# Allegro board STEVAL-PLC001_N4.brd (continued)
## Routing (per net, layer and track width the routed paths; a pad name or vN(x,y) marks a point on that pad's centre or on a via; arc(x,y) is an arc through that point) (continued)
FMC_CTRL.SDNRAS: length 21.1
  TOP w0.2: v2(39.71,69.4) 41.21,70.9 44.6,70.9 46.3,69.2 v1(46.91,69.2)
  BOTTOM w0.2: v2(39.71,69.4) 38.51,70.6 35.22,70.6 34.77,70.15 34.32,70.15 34.27,70.2 U19.19 ; U27.49 50.41,69.5 50.11,69.2 v1(46.91,69.2)
FMC_CTRL.SDNWE: length 21.2
  TOP w0.18: v2(35.31,68.8) 39.01,65.1 45.7,65.1 46.38,65.78 v1(46.91,65.78)
  BOTTOM w0.16: v1(46.91,65.78) 47.39,65.78 48.11,66.5 U27.43 ; v2(35.31,68.8) 34.91,69.2 U19.17
FMC_DATA.D0: length 46.5
  POWER PLANE w0.152: v1(35.12,61.79) 35.88,62.55 35.88,62.88 35.91,62.9 35.91,63.77 36.47,64.32 36.47,75.23 42.43,81.19 42.43,81.2 42.86,81.63 42.87,81.63 45.58,84.34 56.54,84.34 56.54,84.34 59.36,84.34 59.38,84.35 59.71,84.35 v1(60.41,85.05)
  BOTTOM w0.152: U19.2 35.03,61.7 v1(35.12,61.79) ; v1(60.41,85.05) 60.07,84.71 60.07,84.57 59.86,84.35 U27.85
FMC_DATA.D1: length 44.8
  POWER PLANE w0.152: v1(60.48,84.24) 60.03,84.24 59.84,84.05 59.5,84.05 59.49,84.04 56.67,84.04 56.66,84.03 45.74,84.03 44.85,83.14 44.84,83.14 43.64,81.94 43.61,81.94 42.99,81.33 42.98,81.33 42.73,81.08 42.73,81.07 36.77,75.1 36.77,64.2 36.76,64.19 36.76,63.9 36.31,63.45 v1(36.31,62.7)
  BOTTOM w0.152: v1(36.31,62.7) U19.4 ; U27.86 60.36,84.12 v1(60.48,84.24)
FMC_DATA.D2: length 59.6
  POWER PLANE w0.16: v1(71.31,78.8) 69.92,78.8 67.25,81.47 67.25,81.87 65.66,83.46 64.41,83.46 63.43,84.44 63.41,84.44 62.06,85.79 61.88,85.79 61.82,85.86 59.92,85.86 59.01,84.95 56.29,84.95 56.29,84.94 45.29,84.94 35.81,75.47 35.81,69.06 35.85,69.02 35.85,68.58 35.81,68.54 35.81,65.1 35.11,64.4 v1(35.11,63.3)
  BOTTOM w0.152: U27.114 72.09,78.5 71.79,78.8 v1(71.31,78.8)
  BOTTOM w0.16: U19.5 35.01,63.2 v1(35.11,63.3)
FMC_DATA.D3: length 58.6
  POWER PLANE w0.152: 36.16,68.42 36.16,75.38 45.42,84.64 56.41,84.64 56.42,84.64 59.24,84.64 60.08,85.48
  POWER PLANE w0.16: v1(35.71,64.2) 36.16,64.65 36.16,68.42 ; v1(71.66,78) 70.28,78 66.94,81.34 66.94,81.74 65.53,83.15 64.28,83.15 63.3,84.13 63.28,84.13 61.93,85.48 60.08,85.48
  BOTTOM w0.152: U27.115 v1(71.66,78)
  BOTTOM w0.16: v1(35.71,64.2) U19.7
FMC_DATA.D4: length 23.2
  TOP w0.152: v2(47.01,72.86) 42.42,72.86 39.49,69.93 39.49,69.93 38.52,68.96 38.52,68.57 v2(37.93,67.98)
  BOTTOM w0.152: v2(47.01,72.86) 48.04,72.86 49.38,74.2 50.87,74.2 51.07,74 U27.58 ; v2(37.93,67.98) 37.52,67.57 37.52,67.5 34.72,64.7 U19.8
FMC_DATA.D5: length 22.9
  TOP w0.152: v2(47.82,73.39) 47.4,73.8 42.72,73.8 v1(37.91,69) 37.91,68.98
  BOTTOM w0.152: v2(47.82,73.39) 47.83,73.4 47.94,73.4 49.04,74.5 49.25,74.5 49.25,74.5 51.07,74.5 51.07,74.5 U27.59 ; U19.10 34.61,65.7 37.66,68.75
  BOTTOM w0.16: v1(37.91,69) 37.66,68.75
FMC_DATA.D6: length 22.8
  TOP w0.152: 37.81,69.7 42.3,74.2 v2(47.81,74.2)
  TOP w0.16: v1(37.52,69.42) 37.81,69.7
  BOTTOM w0.152: v2(47.81,74.2) 48.31,74.2 49.11,75 U27.60 ; U19.11 34.3,66.2 v1(37.52,69.42) 37.66,69.56
FMC_DATA.D7: length 27.1
  TOP w0.16: 45.65,78.09 v2(47.82,78.09)
  TOP w0.17: 45.65,78.09 39.7,78.09 33.91,72.3 33.91,71.48 33.89,71.45 33.89,71.14 33.91,71.12 v2(33.91,67.2)
  BOTTOM w0.16: v2(47.82,78.09) 48.22,78.09 49.81,76.5 U27.63
  BOTTOM w0.17: v2(33.91,67.2) U19.13
FMC_DATA.D8: length 17.3
  POWER PLANE w0.18: v1(52.98,77) 52.49,77 52.49,77 49.52,77 48.03,75.5 48.03,75.48 46.46,73.91 46.46,71.75 46.91,71.3 v1(46.91,70.8)
  BOTTOM w0.18: U19.74 45.04,67.2 45.71,67.87 45.71,69.11 46.91,70.31 v1(46.91,70.8)
  BOTTOM w0.2: v1(52.98,77) U27.64
FMC_DATA.D9: length 16.7
  POWER PLANE w0.18: v1(50.91,77.5) 49.56,77.5 47.7,75.63 47.7,75.61 45.46,73.38 45.46,70.16 45.51,70.11 v1(45.51,66.25)
  BOTTOM w0.2: v1(50.91,77.5) U27.65 ; v1(45.51,66.25) 45.46,66.25 45.41,66.2 U19.76
FMC_DATA.D10: length 19.9
  POWER PLANE w0.18: v1(52.98,78) 49.59,78 47.37,75.77 47.37,75.75 45.06,73.45 45.06,65.8 v1(45.26,65.6)
  BOTTOM w0.2: U19.77 45.06,65.7 45.16,65.6 v1(45.26,65.6) ; v1(52.98,78) U27.66
FMC_DATA.D11: length 20.2
  POWER PLANE w0.18: v1(45.51,64.65) 45.02,64.65 44.7,64.97 44.7,73.55 47.04,75.89 47.04,75.91 49.63,78.5 v1(50.91,78.5)
  BOTTOM w0.2: v1(45.51,64.65) 45.46,64.7 U19.79 ; U27.67 v1(50.91,78.5)
FMC_DATA.D12: length 22.9
  POWER PLANE w0.18: v1(52.98,79) 49.66,79 46.71,76.05 46.71,76.02 44.3,73.62 44.3,70.8 44.26,70.76 44.26,64.89 44.98,64.17 v1(45.16,64.17)
  BOTTOM w0.2: U27.68 v1(52.98,79) ; U19.80 45.13,64.2 v1(45.16,64.17)
FMC_DATA.D13: length 29.9
  BOTTOM w0.16: U27.77 55.86,66.23 52.43,62.8 45.37,62.8 44.97,63.2 U19.82
FMC_DATA.D14: length 30.7
  BOTTOM w0.16: U27.78 56.36,66.3 52.26,62.2 45.53,62.2 45.03,62.7 U19.83
FMC_DATA.D15: length 31.1
  BOTTOM w0.17: U19.85 52.21,61.7 56.86,66.34 56.86,66.73 56.86,66.74 U27.79
I0.0: length 32.7
  TOP w0.2: R7.1 31.91,104.55 v2(33.41,106.05)
  BOTTOM w0.25: v2(33.41,106.05) 34.11,106.75 34.11,114.2 32.16,116.15 19.34,116.15
  BOTTOM w0.5: J1.8 19.34,116.15
I0.1: length 22
  TOP w0.2: v2(29.71,105.15) 29.71,103.55 30.31,102.95 R9.1
  BOTTOM w0.25: 23.87,115.6 28.06,115.6 29.71,113.95 v2(29.71,105.15)
  BOTTOM w0.5: J1.7 23.87,115.6
I0.2: length 11.9
  TOP w0.2: R11.1 v2(28.71,105)
  BOTTOM w0.25: 28.71,110.94 v2(28.71,105)
  BOTTOM w0.5: J1.6 28.71,110.94
I0.3: length 13.5
  TOP w0.2: 27.11,104.29 R12.1
  TOP w0.25: v2(30.31,106.24) 29.06,106.24 27.11,104.29
  BOTTOM w0.25: 31.59,113.14 J1.5 ; v2(30.31,106.24) 31.59,107.52 31.59,108.98
  BOTTOM w0.5: 31.59,108.98 31.59,113.14
I0.4: length 21.7
  TOP w0.25: R14.1 25.46,102.88 24.96,103.38 24.96,108.07 25.21,108.32 v2(34.97,108.32)
  BOTTOM w0.25: v2(34.97,108.32) 34.97,109.26 36.67,110.96 ; 36.67,113.14 J1.4
  BOTTOM w0.5: 36.67,110.96 36.67,113.14
I0.5: length 25.8
  TOP w0.25: R17.1 23.86,108 24.77,108.91 v2(36.63,108.91)
  BOTTOM w0.25: v2(36.63,108.91) 37.57,108.91 39.16,110.5 39.16,110.57
  BOTTOM w0.5: 39.16,110.57 J1.3
I0.6: length 32.1
  TOP w0.25: v2(41.31,109.66) 24.49,109.66 23.46,108.62 23.46,104.2 22.31,103.05 R19.1
  BOTTOM w0.25: v2(41.31,109.66) 43.28,109.66 44.81,111.18 44.85,111.18
  BOTTOM w0.5: 44.85,111.18 J1.2
I0.7: length 38.3
  TOP w0.25: J1.1 49.21,110.46 24.51,110.46 23.01,108.96 23.01,105.1 20.76,102.85 R22.1
I1.0H: length 16.7
  TOP w0.25: 54.85,101.5 54.89,101.54 C20.1 56.74,101.82 56.75,101.82 57.09,102.16 57.09,102.17 57.81,102.89 57.81,108.53 J6.2
  TOP w0.3: U4.6 U4.7
I1.0L: length 12.7
  TOP w0.25: C20.2 55.98,102.46 55.55,102.02 U4.8
  TOP w0.3: v2(56.91,103.2) 56.46,102.75 C20.2
  BOTTOM w0.25: v2(56.91,103.2) 58.91,105.2 63.46,105.2 J6.5
I1.1H: length 25.8
  TOP w0.25: C23.1 64.15,99.04 67.86,102.75 J6.1
  TOP w0.3: C23.1 55.46,99.04 55.45,99.02 U4.2 U4.3
I1.1L: length 17.8
  TOP w0.25: U4.4 55.91,100.02 55.97,99.96 C23.2
  TOP w0.3: C23.2 56.56,100.05 57.06,100.55 v2(57.06,100.71)
  BOTTOM w0.25: v2(57.06,100.71) 57.82,99.95 67.01,99.95 J6.4
I1.2H: length 31.7
  TOP w0.2: C26.1 94.92,101.44 94.81,101.55 U5.7 U5.6
  TOP w0.25: C26.1 96.12,101.44 96.31,101.62 96.31,102.9 92.91,106.3 80.85,106.3 J7.3
I1.2L: length 23.4
  TOP w0.2: U5.8 94.61,102.05 94.92,102.36 C26.2
  TOP w0.25: J7.6 77.75,105.5 92.37,105.5 C26.2
I1.3H: length 30
  TOP w0.25: J7.2 85.18,107.05 93.36,107.05 96.91,103.5 96.91,100.15 95.8,99.04 C28.1
  TOP w0.3: C28.1 95.5,99.05 U5.2 U5.3
I1.3L: length 19.9
  TOP w0.3: v2(95.81,100.7) 95.81,100.4 95.51,100.1 C28.2 95.4,99.96 95.31,100.05 U5.4
  BOTTOM w0.25: J7.5 82.53,105.2 91.31,105.2 92.51,104 92.68,104 94.66,102.01 94.66,101.84 v2(95.81,100.7)
I2C1_SCL: length 17.2
  POWER PLANE w0.16: v1(75.41,82.45) 75.36,82.45 74.17,81.26 74.17,68.16 74.27,68.07 v1(74.27,67.59)
  BOTTOM w0.16: v1(75.41,82.45) R105.2 ; U27.136 74.01,67.5 74.1,67.59 v1(74.27,67.59)
I2C1_SDA: length 15.5
  POWER PLANE w0.16: v1(75.41,79.9) 74.48,78.97 74.48,75.63 74.7,75.41 74.7,67.28 v1(74.27,66.85)
  BOTTOM w0.16: v1(74.27,66.85) 74.12,67 U27.137 ; v1(75.41,79.9) R108.2
IN1_FLT: length 22.4
  TOP w0.16: R33.1 75.37,22.65 75.29,22.57 74.26,22.57 73.76,23.07 C33.2 73.24,22.57 72.82,22.57 72.64,22.39 72.48,22.39 72.14,22.05 U8.4
  TOP w0.2: 78,25.15 77.6,24.75 77.51,24.75 76.49,23.73 76.45,23.73 R33.1 ; 78.21,25.15 D17.A
  TOP w0.3: D17.A 77.18,25.15 v1(76.49,24.46)
  LOGIC_PLANE w0.2: v1(67.71,20.64) 67.71,21.82 69.1,23.2 71.11,23.2 71.31,23.4 75.93,23.4 76.49,23.96 v1(76.49,24.46)
  BOTTOM w0.2: v1(67.71,20.64) 67.71,20.75 68,21.04 R57.2
IN2_FLT: length 20.4
  TOP w0.16: 72.21,25.14 72.21,25.15 72.59,25.53 72.59,25.83 72.86,26.1 73.31,26.1 73.56,25.85 73.56,25.03 74.28,24.31 74.28,24.29 R35.1 ; 72.82,23.09 C32.2 ; 72.82,23.09 72.82,23.01 72.61,22.8 72.46,22.8 72.04,22.39 71.9,22.39 71.79,22.27 71.49,21.97 U8.5 ; 72.82,23.09 72.39,23.52 72.39,24.31 72.21,24.49 72.21,24.75
  TOP w0.2: v1(72.11,25.77) 72.11,25.25 72.21,25.15
  TOP w0.25: 72.21,24.75 72.21,25.14 D18.A
  BOTTOM w0.2: R56.2 66.57,21.53 66.57,22.22 66.75,22.4 66.75,22.96 66.51,23.2 66.51,25.57 66.71,25.77 v1(72.11,25.77)
IN3_FLT: length 29.2
  TOP w0.2: C38.2 70.91,22.75 70.83,22.67 U8.6 ; C38.2 v1(71.25,22.75) ; C38.2 R41.1 ; 71.91,22.87 71.91,23.04 R41.1 ; R41.1 71.86,22.98 71.79,22.91 ; D19.A 70.7,25.62 70.71,25.63 70.71,25.64 ; 70.71,25.64 v3(70.71,26.25) 70.7,26.24 70.7,25.63 70.71,25.64
  POWER PLANE w0.2: v3(70.71,26.25) 70.71,25.45 71.79,24.37 71.79,22.91 71.42,22.91 v1(71.25,22.75)
  POWER PLANE w0.3: v3(70.71,26.25) 70.71,26.91 69,28.62 60.29,28.62 TP8.1
  LOGIC_PLANE w0.2: v1(71.25,22.75) 71.61,22.39 72.06,22.39 73.35,21.1 73.35,20.94 v1(73.85,20.44)
  BOTTOM w0.2: R53.2 73.46,20.83 v1(73.85,20.44)
IN4_FLT: length 18.2
  TOP w0.16: U8.7 69.96,21.26 69.96,20.76 69.77,20.57 69,20.57 68.65,20.22 68.65,19.74 v1(68.31,19.4)
  TOP w0.2: v1(69.06,22.52) R43.1 C39.2 69.96,22.84 70.16,22.64 70.16,22.6 70.18,22.58 U8.7
  TOP w0.25: D20.A 64.41,25.11 v1(64.41,25.6)
  POWER PLANE w0.2: 64.68,25.6 66.52,25.6 69.06,23.05 v1(69.06,22.52)
  POWER PLANE w0.25: 64.68,25.6 v1(64.41,25.6)
  BOTTOM w0.2: R50.2 72.22,20.45 69.36,20.45 v1(68.31,19.4)
IO-RST: length 48.4
  LOGIC_PLANE w0.16: v1(65.33,87.86) 65.33,88.34 67.57,90.57 83.27,90.57 89.91,83.93 89.91,76.21 89.94,76.18 89.94,70.52 90.64,69.82 v2(90.64,69)
  BOTTOM w0.152: 90.67,69.12 90.64,69.09 v2(90.64,69)
  BOTTOM w0.16: v1(65.33,87.86) 65.33,87.61 66.01,86.93 R164.2
  BOTTOM w0.3: R122.1 R123.1
IRQ: length 116.4
  POWER PLANE w0.16: v1(81.91,55.52) 81.32,56.1 v1(81.32,86.6)
  LOGIC_PLANE w0.2: v1(71.71,51.3) 72.41,51.3 76.61,55.5 81.39,55.5 81.41,55.52 v1(81.91,55.52) ; v1(39.61,50.3) 39.11,49.8 39.11,48.25 41.43,45.93 46.43,45.93 v1(46.78,45.58)
  BOTTOM w0.16: 89.97,56.4 88.91,56.4 88.03,55.52 v1(81.91,55.52) ; v1(81.32,86.6) 80.93,86.2 76.53,86.2 75.81,86.92 74.52,86.92 R162.2
  BOTTOM w0.18: 89.97,56.4 R134.1
  BOTTOM w0.2: R99.2 38.31,48.54 38.31,49 v1(39.61,50.3) 38.21,50.3 36.71,51.8 34.17,51.8 ; v1(46.78,45.58) 50.33,45.58 52.31,43.6 61.37,43.6 62.77,45 69.83,45 70.17,45.34 71.45,45.34 72.51,46.4 72.51,49.8 71.71,50.6 v1(71.71,51.3)
  BOTTOM w0.3: R187.1 34.17,51.8
L+ON: length 90.7
  TOP w0.2: v2(58.71,73.6) 58.28,73.17 58.28,73.16 R165.2 54.62,70.09 54.51,70.2 v2(54.51,79.6)
  LOGIC_PLANE w0.2: v1(71.51,66.5) 72.01,66.5 72.11,66.4 75.58,66.4 75.62,66.36 76.35,66.36 77.31,65.4 v1(78.11,65.4) ; v1(49.91,90.8) 51.31,89.4 51.31,88 54.51,84.8 v2(54.51,79.6)
  LOGIC_PLANE w0.3: v1(37.51,89.6) 36.21,88.3 36.16,88.3 v1(35.81,87.95)
  BOTTOM w0.2: v2(58.71,73.6) 65.81,66.5 v1(71.51,66.5) ; v1(37.51,89.6) 38.71,90.8 v1(49.91,90.8)
  BOTTOM w0.25: v1(78.11,65.4) 78.48,65.77 82.67,65.77 83.11,65.33 83.11,63 84.98,61.12 88.01,61.12 88.01,61.12 89.45,61.12 R131.1 91.51,59.06 91.51,55.44 R135.1
  BOTTOM w0.3: R140.1 35.37,87.95 v1(35.81,87.95)
LCD_BLUE2: length 18
  TOP w0.16: U17.13 46.85,58.08 46.94,57.99 46.94,57.99 49.6,55.34 49.68,55.25 50.21,55.25 50.46,55.25 50.47,55.25 50.5,55.25 50.77,55.25 50.79,55.25 51.06,55.25 51.89,55.25 53.3,53.84 54.01,53.84 54.27,53.58 54.27,53.57 54.39,53.45 U15.23
  TOP w0.18: v1(50.25,48.66) 51.18,48.66 53.27,50.75 53.27,50.78 53.53,51.04 53.56,51.04 54.39,51.87 U15.23
  BOTTOM w0.18: R193.1 v1(50.25,48.66)
LCD_BLUE3: length 11.7
  TOP w0.152: U17.14 46.88,58.48 49.8,55.56 50.33,55.56 50.63,55.56 50.63,55.56 51.03,55.56 52.28,55.56 53.66,54.18 54.48,54.18 54.89,53.77 U15.24
LCD_BLUE4: length 12.3
  TOP w0.152: U17.15 47,58.88 50.02,55.86 50.33,55.86 50.56,55.86 50.75,55.86 50.96,55.86 51.16,55.86 52.4,55.86 53.78,54.48 54.68,54.48 55.39,53.77 U15.25
LCD_BLUE5: length 13
  TOP w0.152: U15.26 55.89,53.77 54.88,54.78 53.91,54.78 52.53,56.16 51.09,56.16 50.88,56.16 50.69,56.16 50.46,56.16 50.14,56.16 47.03,59.28 U17.16
LCD_BLUE6: length 6.8
  TOP w0.152: U16.9 52.78,56.49 53.04,56.23 55.37,56.23 56.14,55.46 56.14,55.14 56.39,54.89 U15.27
LCD_BLUE7: length 7.5
  TOP w0.152: U15.28 56.89,54.82 56.44,55.27 56.44,55.62 55.42,56.64 53.92,56.64 53.85,56.7 53,56.7 52.81,56.89 U16.10
LCD_BLUE.B3: length 36.9
  TOP w0.152: v1(45.51,60.18) 45.7,60.37 46.78,60.37 46.97,60.18
  TOP w0.16: v3(44,58.56) 44.01,58.55 44.35,58.55 44.75,58.55 U17.3 ; 46.97,60.18 47.24,59.91 49.89,59.91 51.84,61.87 54.42,61.87 58.82,66.26 64.01,71.45 69.46,71.45 v1(70.51,72.5)
  POWER PLANE w0.16: v1(45.51,60.18) 44.46,60.18 44,59.72 v3(44,58.56)
  BOTTOM w0.16: v1(70.51,72.5) U27.126
LCD_BLUE.B4: length 36
  TOP w0.16: v1(69.11,72) 64.12,72 58.69,66.57 58.69,66.57 54.3,62.18 51.72,62.18 49.97,60.43 49.88,60.43 49.87,60.43 48.32,60.43 47.77,60.99 45.13,60.99 44.24,60.1 44.24,59.24 44.53,58.95 44.57,58.95 44.64,58.88 U17.2
  BOTTOM w0.16: U27.127 v1(69.11,72)
LCD_BLUE.B5: length 13.4
  TOP w0.152: U17.1 44.82,60.09 45.4,60.67 47.28,60.67 v1(47.55,60.4)
  LOGIC_PLANE w0.16: 49.81,63.5 47.55,61.24 v1(47.55,60.4)
  LOGIC_PLANE w0.17: v1(53.12,64.19) 52.71,64.6 50.91,64.6 49.81,63.5
  BOTTOM w0.17: U27.37 52.68,63.5 53.12,63.94 v1(53.12,64.19)
LCD_BLUE.B6: length 35.3
  TOP w0.152: U16.8 51.07,56.49 50.98,56.49 50.91,56.56 50.88,56.56 50.33,56.56 48.47,58.42 v1(48.47,58.9)
  TOP w0.158: v1(49.76,60.86) 51.41,62.52 52.52,62.52
  TOP w0.16: v1(59.41,68.5) 59,68.09 58.2,68.09 52.63,62.52 52.52,62.52
  BOTTOM w0.158: v1(48.47,58.9) 48.47,59.58 v1(49.76,60.86)
  BOTTOM w0.16: v1(59.41,68.5) 59.41,69.1 59.71,69.4 62.39,69.4 65.79,66 U27.139
LCD_BLUE.B7: length 34.3
  TOP w0.16: v1(49.12,59.46) 49.12,58.22 49.64,57.71 50.42,56.93 50.98,56.93 51.02,56.89 U16.7 ; v1(49.15,60.86) 51.18,62.9 52.46,62.9 52.63,63.07 52.69,63.07 52.94,63.32 52.94,63.38 58.7,69.14 59.77,69.14 v1(60.11,68.8)
  POWER PLANE w0.18: v1(49.15,60.86) 49.15,59.97 49.12,59.95 v1(49.12,59.46)
  BOTTOM w0.16: U27.140 65.86,65.5 62.56,68.8 v1(60.11,68.8)
LCD_CLK: length 40.1
  TOP w0.152: v1(49.67,58.59) 49.67,58.11 49.73,58.06 49.73,58.05 49.94,57.84 50.49,57.29 U16.6
  POWER PLANE w0.16: v1(63.36,79.4) 63.36,60.2 62.61,59.45 61.09,59.45 61.06,59.42 60.7,59.42 60.67,59.45 59.38,59.45 58.56,60.27 56.64,60.27 56.23,59.86 54.65,59.86 54.02,59.23 50.79,59.23 50.15,58.59 v1(49.67,58.59)
  BOTTOM w0.16: U27.92 v1(63.36,79.4)
LCD_CLK2: length 8.7
  TOP w0.18: U15.30 57.89,54.28 57.44,54.73 57.44,55.73 57.31,55.86 57.31,55.87 57.05,56.13 57.04,56.13 56.22,56.95 54.05,56.95 53.98,57.02 53.13,57.02 52.86,57.29 U16.11
LCD_DE: length 12.9
  TOP w0.152: v1(60.83,60.56) 60.34,61.05 54.06,61.05 53.27,60.25 51.52,60.25 50.72,59.45 50.72,59.25 50.72,59.13 50.93,58.92 51.04,58.92 51.07,58.89 U16.2
  BOTTOM w0.2: v1(60.83,60.56) 60.86,60.59 U27.22
LCD_DE2: length 11.9
  TOP w0.18: U16.15 56.15,58.89 57.35,57.69 58.38,57.69 58.84,57.23 58.84,56.81 59.89,55.76 U15.34
LCD_DISP: length 36.1
  TOP w0.152: U16.5 50.52,57.69 50.49,57.71 50.11,58.09 50.11,59.71 50.17,59.76 50.63,60.22 51.51,61.1 51.97,61.56
  TOP w0.158: 55.59,62.59 54.55,61.56 51.97,61.56
  TOP w0.16: 55.59,62.59 58.94,65.95 58.95,65.95 64.14,71.14 70.05,71.14 v1(74.91,76)
  BOTTOM w0.16: v1(74.91,76) U27.119
LCD_DISP2: length 9.5
  TOP w0.152: U15.31 58.39,54.81 57.77,55.43 57.77,55.86 56.36,57.27 54.23,57.27 53.6,57.9 53.06,57.9 52.85,57.69 U16.12
LCD_GREEN2: length 12.6
  TOP w0.152: U15.15 50.39,53.46 50.13,53.72 49.32,53.72 49.07,53.72 49.05,53.74 48.76,54.03 48.75,54.03 48.75,54.03 48.66,54.12 47.49,55.29 41.36,55.29 41.06,55.59 U18.15
LCD_GREEN3: length 12.7
  TOP w0.152: U18.16 41.46,55.89 41.61,55.74 47.47,55.74 48.7,54.5 48.88,54.33 48.89,54.33 49.17,54.04 49.2,54.02 49.49,54.02 50.5,54.02 50.89,53.63 U15.16
LCD_GREEN4: length 8
  TOP w0.16: v1(46.4,56.21) 46.13,56.48 U17.9 ; U15.17 v1(51.39,52.01)
  LOGIC_PLANE w0.16: v1(46.4,56.21) 47.19,56.21 v1(51.39,52.01)
LCD_GREEN5: length 8
  TOP w0.152: U15.18 51.89,53.77 51.34,54.32 49.66,54.32 49.32,54.32 49.01,54.63 49,54.63 46.76,56.88 U17.10
LCD_GREEN6: length 8.7
  TOP w0.152: U15.19 52.39,53.77 51.53,54.62 49.83,54.62 49.45,54.62 49.14,54.93 49.13,54.93 46.78,57.28 U17.11
LCD_GREEN7: length 9.3
  TOP w0.152: U17.12 46.82,57.68 49.55,54.95 50.21,54.95 50.34,54.95 50.38,54.95 50.94,54.95 51.71,54.95 52.89,53.77 U15.20
LCD_GREEN.G2: length 14.3
  TOP w0.152: v1(42.11,60) 41.91,59.8 41.58,59.8 41.06,59.28 U18.2
  LOGIC_PLANE w0.152: v1(50.3,66.01) 49.97,65.67 49.93,65.67 45.26,61 43.36,61 42.7,60.34 42.45,60.34 v1(42.11,60)
  BOTTOM w0.152: v1(50.3,66.01) 50.81,66.01 50.81,66 U27.42
LCD_GREEN.G3: length 38.4
  TOP w0.152: 69.31,73 v1(68.92,73) 62.16,73 58.87,69.71 58.83,69.71 53.74,64.62 52.46,64.62 49.16,61.32 49.13,61.32 49.12,61.31 47.22,61.31 47.22,61.31 43.77,61.31 42.73,60.27 42.73,60.09 42.54,59.9 42.54,59.82 42.16,59.45 41.91,59.45 41.46,59 U18.1
  BOTTOM w0.16: v1(68.92,73) U27.125
LCD_GREEN.G4: length 35.7
  TOP w0.152: v1(42.08,58.85) 42.08,57.14 42.67,56.55 44.25,56.55 44.32,56.48 U17.8
  TOP w0.16: v1(42.31,60.8) 43.13,61.62 49,61.62 49.05,61.67 49.06,61.67 52.31,64.92 52.58,64.92 v1(53.29,65.62)
  POWER PLANE w0.152: v1(42.31,60.8) 41.94,60.43 41.93,60.43 41.68,60.18 41.68,59.71 42.08,59.32 v1(42.08,58.85)
  BOTTOM w0.152: v1(53.29,65.62) 53.89,66.22 53.89,78.82 53.21,79.5 U27.69
LCD_GREEN.G5: length 37.9
  TOP w0.152: U17.7 43.01,56.88 42.38,57.51 42.38,58.54 42.5,58.67 42.5,58.68 42.53,58.71 42.53,59.22 v1(42.87,59.55)
  TOP w0.16: v1(54.41,66.75) 53.73,66.07 53.01,66.07 48.89,61.95 46.99,61.95 46.99,61.95 v1(42.11,61.95) 42.06,61.95
  LOGIC_PLANE w0.152: v1(42.87,59.55) 42.83,59.55 42.81,59.57 41.93,59.57 41.68,59.82 41.68,59.83 41.54,59.97 41.54,61.38 41.77,61.61
  LOGIC_PLANE w0.16: v1(42.11,61.95) 41.77,61.61
  BOTTOM w0.152: v1(54.41,66.75) 54.41,78.73 53.14,80 U27.70
LCD_GREEN.G6: length 45.7
  TOP w0.152: v1(43.16,59.09) 43.16,59.09 43.16,58.91 42.8,58.56 42.8,58.54 42.68,58.42 42.68,58.1 43.5,57.28 U17.6
  TOP w0.16: v1(42.38,62.43) 42.86,62.43 42.88,62.45 48.95,62.45 52.96,66.46 52.96,66.97 53.21,67.22 53.78,67.22 62.96,76.4 65.81,76.4 v2(65.86,76.35)
  LOGIC_PLANE w0.152: v1(43.16,59.09) 42.5,59.09 42.32,59.27 41.81,59.27 41.79,59.29 41.42,59.29 41.23,59.48 41.23,61.92 41.74,62.43 v1(42.38,62.43)
  BOTTOM w0.152: v2(65.86,76.35) U27.97
LCD_GREEN.G7: length 46.6
  TOP w0.152: U17.5 43.79,57.68 v1(43.16,58.31)
  TOP w0.16: v1(41.96,63.08) 42.44,63.08 42.51,63.01 42.51,63.01 42.75,62.77 48.83,62.77 51.31,65.25 51.31,65.85 52.99,67.53 53.65,67.53 54.49,68.37 54.49,68.37 63.12,77 v1(71.96,77)
  LOGIC_PLANE w0.152: v1(43.16,58.31) 42.68,58.31 42.66,58.33 41.58,58.33 40.91,59 40.91,62.02 v1(41.96,63.08)
  BOTTOM w0.16: v1(71.96,77) U27.117
LCD_HSYNC: length 38.8
  TOP w0.152: 50.91,58.08 50.85,58.14 v1(50.67,58.14)
  TOP w0.16: 50.91,58.08 51.16,58.08 U16.4
  POWER PLANE w0.152: v1(65.36,82.4) 65.36,76.6 65.33,76.57 65.33,76.13 65.36,76.1 65.36,75.35 63.98,73.97 63.98,59.97 63.08,59.08 59.21,59.08 58.37,59.93 57.02,59.93 55.98,58.89 53.93,58.89 53.89,58.92 51.45,58.92 v1(50.67,58.14)
  BOTTOM w0.16: U27.96 v1(65.36,82.4)
LCD_HSYNC2: length 10.3
  TOP w0.152: U15.32 58.89,55.52 58.31,56.1 57.99,56.1 56.52,57.57 54.41,57.57 53.77,58.21 52.94,58.21 52.82,58.09 U16.13
LCD_INT: length 45.4
  TOP w0.16: U15.38 61.89,51.61 60.73,50.45 56.41,50.45 v1(55.53,49.57)
  POWER PLANE w0.16: v1(54.91,51.4) 54.91,51.88 55.68,52.65 57.58,52.65 64.63,59.7 64.63,71.92 66.21,73.5 v1(66.51,73.5)
  LOGIC_PLANE w0.16: v1(55.53,49.57) 54.91,50.2 v1(54.91,51.4)
  BOTTOM w0.2: v1(66.51,73.5) U27.124
LCD_RED2: length 19.3
  TOP w0.18: 38.66,55.28 U18.9
  TOP w0.2: 38.66,55.28 43.51,50.43 46.22,50.43 v1(47.22,51.43) 46.87,51.43 46.39,51.91 U15.7
  BOTTOM w0.2: v1(47.22,51.43) 46.6,50.81 46.07,50.81 44.51,49.25 R93.1
LCD_RED3: length 11.3
  TOP w0.16: U15.8 46.89,53.48 46.63,53.74 40.68,53.74 39.06,55.36 U18.10
LCD_RED4: length 11.4
  TOP w0.16: U18.11 39.46,55.4 40.81,54.05 46.68,54.05 46.82,54.05 47.39,53.48 U15.9
LCD_RED5: length 11.4
  TOP w0.16: U15.10 47.83,52.89 47.82,53.54 47.01,54.36 46.81,54.36 40.94,54.36 39.86,55.44 U18.12
LCD_RED6: length 11.5
  TOP w0.16: U15.11 48.39,53.47 47.19,54.67 46.94,54.67 41.06,54.67 40.26,55.48 U18.13
LCD_RED7: length 11.6
  TOP w0.16: U15.12 48.77,52.96 48.77,53.58 48.64,53.72 48.62,53.72 48.62,53.73 48.61,53.73 48.45,53.89 47.36,54.98 41.19,54.98 40.66,55.51 U18.14
LCD_RED.R2: length 21.5
  TOP w0.152: U18.8 38.66,58.83 38.38,59.11 37.55,59.11 37.03,58.59 v1(37.03,58.11)
  POWER PLANE w0.17: 53.95,58.08 53.93,58.07 53.92,58.07 v1(53.31,57.46) 52.83,57.46 52.73,57.36 39.53,57.36 38.31,58.59 37.51,58.59 v1(37.03,58.11)
  BOTTOM w0.2: v1(53.31,57.46) 53.42,57.46 53.62,57.66 53.62,57.67 53.64,57.69 53.64,57.77 R152.2
LCD_RED.R3: length 20.5
  TOP w0.152: v3(38.91,60.3) 38.91,59.42 39.06,59.27 U18.7
  TOP w0.16: v3(39.26,62.1) 40.76,63.6 42.56,63.6 43.06,63.1 43.28,63.1 43.29,63.09 48.71,63.09 50.91,65.29 v1(50.91,67.6)
  POWER PLANE w0.152: v3(38.91,60.3) 38.91,61.17 39.26,61.52 v3(39.26,62.1)
  BOTTOM w0.16: U27.46 51.31,68 v1(50.91,67.6)
LCD_RED.R4: length 19.1
  TOP w0.152: 49.75,64.56 49.75,64.89 v1(50.09,65.22)
  TOP w0.16: U18.6 39.46,60.8 38.76,61.5 38.76,61.84 38.72,61.88 38.72,62.32 40.35,63.95 42.76,63.95 43.3,63.41 43.41,63.41 43.42,63.4 48.59,63.4 49.75,64.56
  BOTTOM w0.16: v1(50.09,65.22) 50.57,65.22 50.84,65.5 U27.41
LCD_RED.R5: length 24.1
  TOP w0.152: v3(40.56,62) 39.86,61.3 U18.5
  POWER PLANE w0.17: v1(58.86,60.62) 56.54,60.62 56.11,60.19 55.05,60.19 55.04,60.18 54.68,60.18 54.67,60.19 54.35,60.19 53.14,61.4 50.32,61.4 50.31,61.42 44.74,61.42 44.57,61.59 43.35,61.59 43.01,61.25 41.31,61.25 v3(40.56,62)
  BOTTOM w0.17: v1(58.86,60.62) U27.26
LCD_RED.R6: length 21.7
  TOP w0.152: U18.4 40.26,60.05 40.43,60.22 v3(40.43,60.8)
  TOP w0.16: 49.91,67.02 49.87,66.98 49.87,65.81 49.34,65.28 49.34,64.59 48.46,63.71 43.55,63.71 42.96,64.3 v3(39.86,64.3)
  TOP w0.17: 49.9,67.6 v1(49.91,67.6) 49.91,67.02
  POWER PLANE w0.152: v3(39.86,64.3) 39.86,63.52 39.91,63.47 39.91,61.32 v3(40.43,60.8)
  BOTTOM w0.152: v1(49.91,67.6) 50.25,67.94 50.25,67.95
  BOTTOM w0.2: U27.47 50.8,68.5 50.25,67.95
LCD_RED.R7: length 51.2
  TOP w0.152: v3(40.96,60.05) 40.96,59.95 40.66,59.65 U18.3
  POWER PLANE w0.16: v1(62.8,83.9) 62.39,84.31 61.22,84.31 60.65,83.74 59.97,83.74 59.96,83.74 59.63,83.74 59.62,83.73 56.79,83.73 56.79,83.73 45.87,83.73 44.97,82.83 44.97,82.83 43.59,81.45 43.59,80.72 43.34,80.47 42.57,80.47 37.07,74.97 37.07,61.14 38.57,59.64 40.55,59.64 v3(40.96,60.05)
  BOTTOM w0.16: U27.91 62.86,83.55 62.8,83.61 v1(62.8,83.9)
LCD_RST: length 127.1
  TOP w0.16: v1(61.31,63.82) 61.31,63.26 C127.2
  TOP w0.18: R182.1 60.89,64.23 v1(61.31,63.82)
  TOP w0.2: U15.37 61.39,51.58 60.59,50.78 54.72,50.78 50.67,46.73 49.63,46.73 49.63,46.73 49.25,46.73 49.25,46.73 45.84,46.73 44.58,47.99 40.5,47.99 40.06,48.43 40.06,51.38 38.72,52.72 36.52,52.72 ; v1(53.68,59.71) 54.18,59.71 54.21,59.74 54.85,59.74 55.31,60.2 57.91,60.2 57.95,60.17 59.05,60.17 59.08,60.2 59.11,60.2 59.15,60.24 59.16,60.24 v1(59.51,60.59)
  TOP w0.3: 36.51,52.72 36.52,52.72 36.93,53.13 36.93,56.04 36.55,56.42 D49.C
  TOP w0.4: v1(34.95,51.16) 36.51,52.72
  POWER PLANE w0.3: v1(34.95,51.16) 35.59,51.8 35.59,52.6 35.59,52.6 v1(35.59,55.6) 35.59,57.6 36.96,58.98 38.46,58.98 39.69,57.75 48.12,57.75 49.33,58.96 50.67,60.3 52.95,60.3 53.15,60.1 53.29,60.1 v1(53.68,59.71)
  LOGIC_PLANE w0.18: 71.16,63.29 63.07,63.29 63.04,63.32 61.8,63.32 v1(61.31,63.82)
  LOGIC_PLANE w0.2: v1(85.31,63.4) 77.36,63.4 77.25,63.29 71.16,63.29
  BOTTOM w0.18: v1(61.31,63.82) 59.98,62.49 59.66,62.49 59.36,62.19 U27.25
  BOTTOM w0.2: 95.47,67.32 91.55,63.4 ; v1(59.51,60.59) 59.51,60.6 59.36,60.75 U27.25
  BOTTOM w0.25: 91.55,63.4 v1(85.31,63.4)
  BOTTOM w0.3: J23.10 95.47,67.32 ; SW2.1 29.26,52.3 32.28,52.3 v1(35.59,55.6)
  BOTTOM w0.4: v1(34.95,51.16) 33.19,49.4 R186.1
LCD_SCL: length 35.6
  TOP w0.152: 62.56,55.17 62.39,55 U15.39
  TOP w0.16: 59.02,62.69 v1(59.06,62.65) 59.95,61.76 61.08,61.76 62.56,60.28 62.56,55.17
  BOTTOM w0.152: U27.81 57.86,81.97 57.73,81.84 57.73,63.78 58.35,63.16 58.55,63.16 v1(59.06,62.65)
  BOTTOM w0.25: R167.2 57.51,84.7 57.86,84.35 U27.81
LCD_SDA: length 35.9
  TOP w0.16: v1(59.67,63.06) 60.65,62.07 61.31,62.07 63.41,59.97 63.41,55.54 62.89,55.02 U15.40
  BOTTOM w0.152: U27.82 58.36,81.97 58.03,81.65 58.03,63.91 58.34,63.6 59.12,63.6 v1(59.67,63.06)
  BOTTOM w0.25: U27.82 R169.2
LCD_VSYNC: length 12.6
  TOP w0.152: U16.3 50.92,58.49 50.42,59 50.42,59.58 51.64,60.8 v1(53.11,60.8)
  LOGIC_PLANE w0.2: v1(54.14,65.72) 53.57,65.16 53.57,64.01 53.51,63.95 53.51,61.2 v1(53.11,60.8)
  BOTTOM w0.2: U27.40 53.41,65 v1(54.14,65.72)
LCD_VSYNC2: length 10.9
  TOP w0.152: 59.33,55.55 59.33,53.82 59.39,53.77 U15.33 ; U16.14 52.75,58.49 52.84,58.57 55.94,58.57 57.96,56.56 58.32,56.56
  TOP w0.18: 59.33,55.55 58.32,56.56
OL: length 20.1
  TOP w0.2: U8.9 68.88,20.96 68.02,20.1 v1(67.59,20.1)
  TOP w0.3: v1(60.42,21.34) 60.04,21.73 58.99,21.73 57.45,23.27 57.45,24.49 57.75,24.79 60.71,24.79 61.53,23.98 D22.C
  BOTTOM w0.2: R60.2 61.68,20.42 62.28,20.42 63.3,19.4 65.31,19.4 66.01,20.1 v1(67.59,20.1)
  BOTTOM w0.3: R60.2 60.97,20.99 60.62,21.34 v1(60.42,21.34)
OL-OFF: length 37.1
  POWER PLANE w0.18: v1(55.71,87.8) 54.18,86.27 44.58,86.27 v1(31.91,73.6)
  BOTTOM w0.17: v1(31.91,73.6) 31.11,72.8 31.02,72.8 R95.2
  BOTTOM w0.2: R97.1 55.71,86.14 v1(55.71,87.8)
  BOTTOM w0.3: U27.75 R97.1
OUTN1: length 31.4
  TOP w0.152: 50.55,102.54 R23.1
  TOP w0.25: v2(55.81,100.75) 55.58,100.52 U4.5
  TOP w0.3: v2(51.26,103.25) 50.55,102.54 ; C19.2 R23.1 ; v2(54.16,98.1) 54.16,99.06 U4.TAB1
  BOTTOM w0.3: v2(51.26,103.25) 51.72,103.71 54.8,103.71 55.81,102.7 v2(55.81,100.75) 55.81,99.75 v2(54.16,98.1) 55.21,98.1 60.71,92.6 66.47,92.6 67.28,93.4 U3.2
OUTN2: length 35
  TOP w0.2: R24.1 51.05,100.4 52.02,100.4 52.4,100.02 U4.13
  TOP w0.3: U4.TAB2 53.9,102.79 v2(53.91,102.8) ; C21.2 R24.1 50.21,99.85 50.12,99.94 v2(49.71,99.94)
  BOTTOM w0.3: v2(53.91,102.8) 52.34,101.23 51.89,101.23 51.06,100.4 50.02,100.4 49.71,100.09 ; 49.71,100.09 49.71,99.95 v2(49.71,99.94) ; 49.71,100.09 51.02,100.09 59.11,92 67.14,92 68.55,93.4 U3.3
OUTN3: length 31.8
  TOP w0.2: U5.5 94.46,100.55 v2(94.71,100.8) ; v2(92.91,97.8) 93.01,97.9 U5.TAB1
  TOP w0.25: C25.2 v2(89.6,102.25)
  BOTTOM w0.25: v2(89.6,102.25) 90.95,103.6 92.51,103.6 94.26,101.85 94.26,101.25 v2(94.71,100.8) 94.26,100.35 94.02,100.35 92.91,99.25 v2(92.91,97.8)
  BOTTOM w0.3: v2(89.6,102.25) 88.94,102.25 88.29,101.6 84.55,101.6 83.3,100.35 80.22,100.35 78.5,98.62 78.5,95.54 77.67,94.72 U6.2
OUTN4: length 25.2
  TOP w0.2: v2(92.31,102.8) 93.01,102.1 U5.TAB2
  TOP w0.25: U5.13 91.49,100.05 91.08,100.46 90.79,100.47 90.17,100.47 90.16,100.46 R26.1 C27.2
  BOTTOM w0.25: v2(92.31,102.8) 91.11,101.6 91.11,101.4 v2(89.61,99.9)
  BOTTOM w0.3: U6.3 78.95,98.44 80.41,99.9 v2(89.61,99.9)
OUTP1: length 25.5
  TOP w0.2: U4.11 52.53,101.02 52.26,100.75 49.35,100.75 49.15,100.55 49.15,98.92 49.66,98.41 50.97,98.41 52.19,97.19 54.53,97.19 54.54,97.2 64.29,97.2 64.55,97.45 D9.A
  TOP w0.25: TP5.1 66.76,97.45 D9.A
OUTP2: length 19
  TOP w0.2: D10.A 70.42,97.4 69.33,98.5 64.41,98.5 63.46,97.55 54.4,97.55 54.39,97.54 53.72,97.54 53.41,97.85 53.41,98.19 53.07,98.52 U4.16
OUTP3: length 17.8
  TOP w0.2: U5.11 91.26,101.05 91.11,100.9 90.87,100.9 90.83,100.86 79.2,100.86 75.8,97.45 D11.A
OUTP4: length 11.8
  TOP w0.3: TP6.1 91.01,98.2 91.36,98.55 U5.16
  TOP w0.4: D12.A 81.77,97.45 82.52,98.2 TP6.1
PA1: length 35.9
  POWER PLANE w0.16: v1(75.75,56.64) 74.61,57.78 74.61,64.82 74.71,64.92 v1(74.71,65.4)
  LOGIC_PLANE w0.2: v1(54.59,55.21) 55.03,54.77 55.51,54.77 55.52,54.75 55.9,54.75 55.91,54.77 61.74,54.77 61.84,54.66 64.11,54.66 64.71,55.26 74.37,55.26 v1(75.75,56.64)
  BOTTOM w0.2: R189.2 76.05,56.94 v1(75.75,56.64) ; v1(74.71,65.4) 74.71,65.51 75,65.8 75.85,65.8 R130.2 ; R153.2 53.91,56.19 53.91,55.39 54.09,55.21 v1(54.59,55.21)
PC10: length 22.6
  BOTTOM w0.2: U27.111 74.17,80 74.57,80.4 75.45,80.4 76.45,81.4 89.04,81.4 89.24,81.2 93.31,81.2
  BOTTOM w0.4: J22.2 93.77,81.66 93.31,81.2
PC11: length 21.3
  BOTTOM w0.2: 92.65,78.6 87.91,78.6
  BOTTOM w0.25: 87.91,78.6 74.91,78.6 74.01,79.5 U27.112
  BOTTOM w0.3: 92.91,78.86 92.65,78.6
  BOTTOM w0.4: J24.2 92.91,78.86
PD6/B2: length 38.8
  POWER PLANE w0.16: v2(44.11,85) 44.92,85.81 56.12,85.81 56.13,85.83 59.19,85.83 59.56,86.2 62.11,86.2 64.54,83.77 66.55,83.77 70.07,80.25 70.07,80.24 v1(70.41,79.9)
  BOTTOM w0.16: v2(44.11,85) 44.25,85 R20.1 ; U27.122 70.41,74.5 69.31,75.6 69.31,78.8 v1(70.41,79.9)
PDR_ON: length 3.8
  BOTTOM w0.2: U27.143 74.91,64 75.06,63.85 R179.2
  BOTTOM w0.4: R181.1 76.05,63.8 R179.2
PGOOD: length 10.2
  TOP w0.3: v1(32.24,32.13) 31.65,32.72 R82.2 30.28,32.72 R81.2 ; U13.25 38.79,30.12 v2(38.51,30.4)
  BOTTOM w0.3: v1(32.24,32.13) 33.97,30.4 v2(38.51,30.4)
Q0.0: length 32.8
  TOP w0.152: v2(34.71,18.5) 34.86,18.65 U13.5
  TOP w0.4: v2(34.71,17.3) C59.2
  TOP w0.5: 21.61,10.6 R80.1
  TOP w0.7: 34.66,18.55 34.66,17.3 ; J14.1 21.61,8.29 21.61,10.6
  BOTTOM w0.6: v2(34.71,18.5) v2(34.71,17.3) 34.71,14.6 33.11,13 26.32,13
  BOTTOM w0.8: J14.1 26.32,13
Q0.1: length 28.4
  TOP w0.4: U13.6 35.51,18.75 v2(35.76,18.5) 35.91,18.65 U13.7
  TOP w0.6: v2(35.76,18.5) 35.71,18.45 v2(35.71,17.3) C58.2
  TOP w0.7: J14.2 26.66,8.26 R79.1
  BOTTOM w0.6: v2(35.71,17.3) 35.71,13.8 33.11,11.2 29.6,11.2
  BOTTOM w0.9: J14.2 29.6,11.2
Q0.2: length 26.4
  TOP w0.4: C56.2 36.71,16.41 v2(36.71,17.3) 36.71,18.4 v2(36.81,18.5)
  TOP w0.7: 36.71,18.65 36.66,18.6 36.66,17.35 v2(36.71,17.3) ; R77.1 31.81,8.33 J14.3
  BOTTOM w0.6: 36.71,13.23 v2(36.71,17.3) 36.71,18.4 v2(36.81,18.5)
  BOTTOM w0.9: J14.3 36.71,13.23
Q0.3: length 22.7
  TOP w0.4: v2(37.86,17.4) C52.2
  TOP w0.7: R73.1 33.61,8.2 34.21,7.6 J14.4 ; v2(37.86,17.4) 37.81,17.45 37.81,18.7
  BOTTOM w0.6: 37.86,9.3 v2(37.86,17.4) v2(37.86,18.5)
  BOTTOM w0.9: J14.4 37.86,9.3
Q0.4: length 21.7
  TOP w0.3: U13.12 38.66,18.7 v2(38.91,18.45)
  TOP w0.6: v2(38.91,18.45) C51.2
  TOP w0.7: J14.5 39.29,7.6 38.36,8.53 R70.1
  BOTTOM w0.6: v2(38.91,18.45) 38.91,7.93
  BOTTOM w0.8: 38.91,7.93 39.29,7.55
  BOTTOM w0.9: 39.29,7.55 J14.5
Q0.5: length 24.2
  TOP w0.4: v2(39.96,18.5) 39.91,18.45 v2(39.91,17.4) C49.2
  TOP w0.7: J14.6 43.51,6.51 R67.1 ; v2(39.91,17.4) 39.96,17.45 v2(39.96,18.5) 39.96,18.65
  BOTTOM w0.6: v2(39.96,18.5) 39.91,18.45 v2(39.91,17.4) 39.91,10.11
  BOTTOM w0.9: J14.6 39.91,10.11
Q0.6: length 25.9
  TOP w0.4: 40.96,17.45 41.01,17.5 v2(41.01,18.5) ; v2(40.91,17.4) C48.2
  TOP w0.7: J14.7 49.45,7.6 48.51,8.54 R66.1 ; 40.96,18.7 40.96,18.2 40.91,18.15 40.96,18.1 40.96,17.45
  BOTTOM w0.6: v2(41.01,18.5) 41.01,17.5 v2(40.91,17.4) 40.91,14.19
  BOTTOM w0.9: J14.7 40.91,14.19
Q0.7: length 26.6
  TOP w0.5: 52.21,11.35 52.22,11.34 R63.1
  TOP w0.7: J14.8 52.21,7.97 52.21,14 49.85,16.36 C47.2 U13.18 42.36,20.9 v2(42.56,20.9)
Q1.0: length 17.5
  TOP w0.25: R40.1 67.41,16.2 67.98,16.77 69.65,16.77 69.79,16.77 70,16.55 70,16.52 70.18,16.34 U8.14
  TOP w0.3: R40.1 66.36,14.06 66.1,13.8 D16.C
  TOP w0.8: J13.1 63.43,7.25 63.43,12.01 65.23,13.8 D16.C
Q1.1: length 13.3
  TOP w0.25: 71.21,14.23 71.01,14.43 71.01,15.2 70.83,15.38
  TOP w0.3: U8.15 70.83,15.38 ; R45.1 71.21,14.23
  TOP w0.5: D15.C 70.36,14.33 70.83,14.81 70.83,15.38
  TOP w0.8: J13.2 69.27,8.01 69.27,12.43 70.34,13.5 D15.C
Q1.2: length 25.8
  TOP w0.2: 75.36,13.8 74.71,14.45 74.15,14.45 74.14,14.46 73.76,14.46 73.75,14.45 71.82,14.45 71.49,14.79 U8.16
  TOP w0.3: 75.36,13.8 D14.C
  TOP w0.4: v2(78.91,14.7) 85.01,14.7 85.11,14.6 R38.1 ; D14.C 75.46,13.85 75.91,14.3 v2(75.91,14.6)
  TOP w0.8: J11.1 72.26,9.14 74.35,11.23 74.35,12.17 74.35,12.95 75.2,13.8 75.36,13.8
  BOTTOM w0.4: v2(78.91,14.7) 76.72,14.7 76.62,14.6 v2(75.91,14.6)
Q1.3: length 22.6
  TOP w0.2: U8.17 72.14,15.22 72.51,14.85 74.94,14.85 75.25,15.16 77.2,15.16 78.56,13.8 v2(79.51,13.8)
  TOP w0.4: R37.1 82.86,13.8 D13.C
  TOP w0.5: D13.C v2(79.51,13.8)
  BOTTOM w0.8: v2(79.51,13.8) 79.51,7.93 J11.2
RCC_OSC32_IN: length 3
  BOTTOM w0.2: U27.8 67.86,59.65 68.16,59.35 R173.2
RCC_OSC32_OUT: length 2.9
  BOTTOM w0.2: U27.9 R180.2
RCC_OSC_IN: length 3.7
  BOTTOM w0.18: 60.36,60.69 60.26,60.59 60.26,59.85 60.44,59.67 60.44,59.67 60.7,59.41 60.7,59.41 60.84,59.27
  BOTTOM w0.2: R178.2 60.84,58.27 60.84,59.27 ; U27.23 60.36,60.69 60.36,60.69
RCC_OSC_OUT/TEST: length 0.5
  BOTTOM w0.2: U27.24 59.86,61.09
RX_EXT: length 20.5
  BOTTOM w0.3: R175.1 R174.1
  BOTTOM w0.4: R175.1 93.98,96.96 94.92,97.89 96.8,97.89 97.31,97.38 97.31,88.04 J25.5 95.71,86.44
SDO_DAISY: length 67.8
  POWER PLANE w0.16: v1(58.4,57.05) 57.47,56.12 57.47,54.18 57.16,53.87 v1(38.74,53.87)
  BOTTOM w0.16: 40.69,54.58 39.98,53.87 v1(38.74,53.87)
  BOTTOM w0.18: 46.39,88.17 46.39,88.87 45.66,89.6 41.02,89.6 40.71,89.29 40.71,56.4 40.69,56.38 40.69,54.58
  BOTTOM w0.2: v1(58.4,57.05) 58.16,56.81 R75.1 57.08,56.81 R155.2
SPI2_ISO_MOSI: length 34.5
  POWER PLANE w0.17: 76.31,58.91 76.31,68.26 v1(75.37,69.2)
  POWER PLANE w0.18: v1(76.31,58.42) 76.31,58.91
  LOGIC_PLANE w0.18: v1(56.87,55.69) 57.36,55.2 57.98,55.2 58.01,55.17 63.36,55.17 63.57,55.38 63.57,55.61 63.83,55.87 64.19,55.87 64.26,55.8 73.69,55.8 v1(76.31,58.42)
  BOTTOM w0.17: R121.2 75.57,69 v1(75.37,69.2)
  BOTTOM w0.18: v1(56.87,55.69) 56.76,55.8 56.35,55.8 55.86,56.29 R154.2
SPI2_MISO: length 83.2
  TOP w0.18: R74.1 35.5,32.9 34.5,33.9 ; v1(57.79,59.44) 58.59,58.64 v1(58.8,58.64) ; v1(75.81,66.99) 75.81,65.32 75.75,65.26 75.75,64.82 73.32,62.39 61.23,62.39 60.72,62.9 60.72,62.9 60.11,63.51 58.62,63.51 v1(57.91,62.8)
  TOP w0.2: 34.5,33.9 29.57,33.9 27.41,36.05 27.41,44.45 31.32,48.36 31.32,49.81 v2(36.31,54.8)
  POWER PLANE w0.18: v1(57.79,59.44) 55.37,57.02 38.53,57.02 v2(36.31,54.8)
  BOTTOM w0.18: v1(58.8,58.64) 58.8,58.95 R21.1
  BOTTOM w0.2: v1(75.81,66.99) 75.81,67.21 R126.2 ; v1(57.79,59.44) 57.79,59.94 57.86,60.01 U27.28 57.86,62.42 57.87,62.43 57.87,62.76 v1(57.91,62.8)
SPI2_MORPHO_ISO: length 70.1
  TOP w0.2: v1(40.93,35.44) 40.58,35.09 38.77,35.09 37.83,34.15 R72.1
  POWER PLANE w0.2: v1(65.11,44.2) 64.07,43.16 48.43,43.16 41.28,36.01 41.28,35.79 v1(40.93,35.44) ; v1(74.41,46.29) 74.41,54.53 77.02,57.14 77.02,62.2 78.56,63.74 78.56,65.59 78.31,65.84 v1(78.31,67.2)
  LOGIC_PLANE w0.2: v1(74.41,46.29) 67.2,46.29 v1(65.11,44.2)
  BOTTOM w0.35: R126.1 77.81,67.5 78.11,67.2 v1(78.31,67.2) 79.2,67.2 79.23,67.23 J18.15
SPI2_NSS: length 116
  TOP w0.16: v1(75.31,65) 75.31,65.79 74.7,66.4 74.7,75.08 75.41,75.79 75.41,78.4 73.45,80.36 55.95,80.36 55.82,80.22 v3(55.23,80.22)
  TOP w0.2: R68.1 41.68,33.14 41.68,36.29 v1(40.65,37.33)
  POWER PLANE w0.2: v3(55.23,80.22) 53.59,81.87 53.26,81.87 v1(52.91,82.22)
  BOTTOM w0.152: v1(75.31,65) 75.8,65 R129.2
  BOTTOM w0.18: 53.86,83.05 53.31,83.6 43.71,83.6 41.14,81.03 41.14,37.84 40.99,37.69 40.99,37.68 v1(40.65,37.33)
  BOTTOM w0.2: v1(52.91,82.22) 53.66,82.22 53.86,82.42 U27.73 53.86,83.81 53.67,84 43.56,84 43.36,84.2 R18.1
SPI2_SCK: length 118.1
  TOP w0.16: v1(75.71,73.26) 75.37,73.6 75.37,75.31 75.72,75.66 75.72,78.53 75.71,78.54 75.71,78.6 73.59,80.72 63.18,80.72 63.15,80.75 55.81,80.75 v2(55.09,81.47)
  TOP w0.4: v1(39.51,33.32) 39.46,33.27 R69.1
  BOTTOM w0.152: 76.15,72.66 75.71,73.1
  BOTTOM w0.16: 75.71,73.1 v1(75.71,73.26)
  BOTTOM w0.18: 39.99,33.8 40.57,33.8 41.51,34.74 41.51,80.8 43.92,83.21 47.91,83.21 49.51,81.6 54,81.6 54.01,81.6 54.36,81.95
  BOTTOM w0.2: v2(55.09,81.47) 54.66,81.9 54.41,81.9 54.36,81.95 U27.74 54.36,84.15 54.11,84.4 46.11,84.4 45.12,85.39 U2.3 ; R190.2 R113.2 ; TP9.1 46.71,34.8 40.99,34.8 39.99,33.8
  BOTTOM w0.4: v1(39.51,33.32) 39.99,33.8
SPI5_HOLD: length 26.2
  POWER PLANE w0.18: v1(61.41,50.2) 62.81,50.2 63.82,51.21 v1(63.82,52.74)
  BOTTOM w0.18: v1(61.41,50.2) 53.93,50.2 53.89,50.16 53.53,50.16 53.49,50.2 52.51,50.2 51.71,51 51.71,51.71 51.83,51.83 51.83,52.19 51.51,52.51 51.51,58.51 53.64,60.64 53.64,60.92 53.86,61.14 U27.36
SPI5_MISO: length 16
  BOTTOM w0.23: 61.91,50.72 61.91,53.24 62.48,53.81 62.48,54.61 61.9,55.19 61.9,60.61
  BOTTOM w0.25: 61.91,50.72 63.84,48.78 U20.2 ; 61.9,60.61 61.86,60.65 U27.20
SPI5_MOSI: length 10.5
  BOTTOM w0.25: U27.21 61.36,55.18 62.09,54.45 62.09,53.97 61.31,53.18 U20.5
SPI5_NSS: length 15.7
  BOTTOM w0.2: U20.1 65.12,48.78 63.16,50.74 63.16,53.4 63.25,53.49 63.25,54.93 63.16,55.02 63.16,57.75 62.86,58.05 U27.18
SPI5_SCK: length 10.2
  BOTTOM w0.25: U20.6 62.58,53.13 62.71,53.27 62.71,53.49 62.87,53.65 62.87,54.77 62.36,55.28 U27.19
SPI5_WP: length 39.9
  POWER PLANE w0.152: v1(72.01,74) 72.01,73.57 72.21,73.37 72.21,62.1 72.2,62.09 72.2,46.61 71.36,45.77 v1(69.94,45.77)
  BOTTOM w0.16: v1(69.94,45.77) 69.5,45.33 63.46,45.33 62.58,46.22 U20.3 ; U27.123 v1(72.01,74)
SYS_JTCLK-SWCLK: length 28.6
  POWER PLANE w0.16: v1(89,77.69) 91.76,74.92 95.83,74.92 96.42,74.33 96.42,73.42
  POWER PLANE w0.3: J23.4 95.5,72.5 96.12,72.5 96.42,72.8 96.42,73.42
  LOGIC_PLANE w0.16: v1(89,77.69) 85.68,81 v2(74.91,81)
  BOTTOM w0.16: v2(74.91,81) U27.109
SYS_JTDI: length 39.8
  TOP w0.2: 96.27,69.93 96.47,69.73 96.47,67.94 95.28,66.75 91.96,66.75 91.36,67.35 v3(91.36,70.6)
  TOP w0.3: J23.8 96.27,69.93
  POWER PLANE w0.2: v1(88.33,73.63) v3(91.36,70.6)
  LOGIC_PLANE w0.16: v1(71.81,79.8) 72.45,80.44 82.27,80.44
  LOGIC_PLANE w0.2: v1(88.33,73.63) 88.33,77.18 85.71,79.8 84.27,79.8 84.07,80 82.71,80 82.27,80.44
  BOTTOM w0.2: U27.110 72.21,80.5 71.81,80.1 v1(71.81,79.8)
SYS_JTDO-SWO: length 30.7
  TOP w0.2: 97.1,70.06 97.1,68.07 95.24,66.22 v2(90.71,66.22)
  TOP w0.3: J23.6 96.38,71.2 97.1,70.48 97.1,70.06
  BOTTOM w0.16: 72.64,69 U27.133 74.78,69 75.33,68.44 82.93,68.44 85.05,66.33 90.01,66.33 90.12,66.22 v2(90.71,66.22)
SYS_JTMS-SWDIO: length 31.5
  LOGIC_PLANE w0.16: v1(89.51,76) 89.51,77.95 85.9,81.56 70.38,81.56 v1(70.04,81.9)
  BOTTOM w0.18: v1(89.51,76) 94.06,76 95.47,74.59 J23.2
  BOTTOM w0.2: v1(70.04,81.9) 70.04,82.01 69.9,82.16 69.9,82.84 U27.105
SYS_JTRST: length 17.8
  BOTTOM w0.2: R191.1 89.4,65.8 85.11,65.8 82.79,68.11 75.2,68.11 74.81,68.5 U27.134
TX_EXT: length 11.9
  TOP w0.4: v1(88.53,87.4) 89.03,87.9 89.03,88.03 89.52,88.52 90.17,88.52 J25.2
  BOTTOM w0.3: 88.53,88.52 88.53,88.52
  BOTTOM w0.4: 88.53,88.52 v1(88.53,87.4) 88.53,86.88 R177.2
UART4-RX: length 92.2
  TOP w0.3: v1(84.31,80.4) 84.25,80.46 R109.1
  POWER PLANE w0.18: v1(29.51,70.2) 29.51,71.8 31.47,73.76 31.47,73.78 31.73,74.04 31.75,74.04 44.31,86.6 53.74,86.6 58.5,91.36 69.93,91.36 71.82,93.25 82.91,93.25 83.76,92.4 83.76,91.44 87.83,87.37 87.83,81.3 88.03,81.1
  POWER PLANE w0.3: 88.03,81.1 89.43,79.7
  POWER PLANE w0.5: 89.43,79.7 J24.3
  BOTTOM w0.18: R96.2 30.37,71.06 v1(29.51,70.2)
  BOTTOM w0.3: 90.42,79.4 89.63,79.4 88.03,81 84.91,81 v1(84.31,80.4)
  BOTTOM w0.4: 90.42,79.4 90.91,79.4 J24.3
UART4-TX: length 3.7
  BOTTOM w0.3: J22.3 94.66,84.5 93.67,84.5 R106.1
UART5_RX: length 56.3
  POWER PLANE w0.16: 91.91,53.14 v1(91.91,67.6)
  POWER PLANE w0.2: v1(91.19,51) 91.19,52.42 91.91,53.14
  BOTTOM w0.16: R104.2 70.71,79.56 70.71,78.1 71.31,77.5 U27.116 74.01,77.5 74.5,77.99 77.12,77.99 78.71,76.4 88.11,76.4 88.88,75.63 88.89,75.63 89.14,75.38 89.14,75.37 91.91,72.6 v1(91.91,67.6)
  BOTTOM w0.2: R138.1 v1(91.19,51)
  BOTTOM w0.3: R138.1 R136.1
USART3_RX: length 14
  BOTTOM w0.2: U28.5 91.06,86.91 R176.2
  BOTTOM w0.3: R176.2 92.11,85.84 92.3,85.84 94.27,85.84 95.31,84.8 96.51,84.8 97.51,83.8 97.51,80.92
  BOTTOM w0.4: 97.51,80.92 J24.1
USART3_TX: length 14.9
  BOTTOM w0.3: U28.1 87.25,91.55 86.51,90.8 86.51,87.8 88.21,86.1 90.81,86.1 91.23,85.68 91.23,84.79 91.23,84.78 J22.1
USB.OTG_FS_DM: length 63.9
  POWER PLANE w0.16: v1(86.5,48.1) 86.5,51.02 86.5,51.03 86.5,86.84 82.33,91 v1(72.16,91)
  BOTTOM w0.16: v1(72.16,91) 72.16,90.52 71.62,89.98 71.62,87.47 71.51,87.36 71.51,87.31 R161.2 ; U25.2 89.73,49.27 88.98,49.27 87.81,48.1 v1(86.5,48.1)
USB.OTG_FS_DP: length 68.7
  POWER PLANE w0.16: v1(72.94,92.8) 82.81,92.8 83.31,92.3 83.31,91.44 87.47,87.28 87.47,60.99 87.6,60.86 v1(87.6,56)
  LOGIC_PLANE w0.16: v1(89.13,48.8) 88.25,48.8 87.47,49.58 87.47,55.39 87.6,55.52 v1(87.6,56)
  BOTTOM w0.16: v1(89.13,48.8) 89.26,48.8 U25.1 ; R163.2 66.91,87.02 66.88,87.05 66.88,87.23 66.67,87.44 66.67,89.56 69.91,92.8 v1(72.94,92.8)
USB.OTG_FS_ID: length 72.5
  TOP w0.25: U22.4 94.92,50.35 v1(95.88,51.3)
  POWER PLANE w0.16: 87.12,60.01 87.12,87.09 82.44,91.77 71.43,91.77 v1(70.87,91.21)
  POWER PLANE w0.17: 87.12,60.01 87.12,51.29 87.63,50.78 87.65,50.78 v1(87.99,50.43)
  BOTTOM w0.152: 95.91,51.27 D44.C
  BOTTOM w0.16: v1(70.87,91.21) 69.26,89.6 69.26,87.03 69.26,86.86 R160.2
  BOTTOM w0.2: 93.84,50.6 91.47,50.6 91.31,50.43 90.93,50.43 90.93,50.43 90.55,50.43 90.55,50.43 v1(87.99,50.43)
  BOTTOM w0.25: 93.84,50.6 94.24,51 95.01,51 95.26,51.25 D44.C 95.29,51.3 v1(95.88,51.3)
USB.OTG_FS_VBUS: length 97.2
  TOP w0.2: v1(85.87,58.46) 86.06,58.46 86.45,58.85 87.26,58.85
  TOP w0.25: 93.05,49.7 U22.5
  TOP w0.3: v2(88.91,57.84) 90.9,57.84 91.72,57.02 91.72,53.05 91.36,52.7 D43.C 90.74,52.57 89.76,51.6 v2(89.76,47.78) 91.64,47.78 92.52,48.66 92.52,49.17 93.05,49.7
  TOP w0.4: 87.26,58.85 D46.3 88.71,58.85 89.11,58.45 89.11,58.04 v2(88.91,57.84)
  POWER PLANE w0.16: v1(82.56,86.55) 81.76,85.75 81.76,59.5 82.78,58.48 85.12,58.48 85.14,58.46 v1(85.87,58.46)
  BOTTOM w0.152: R192.1 78.51,38.35 77.96,37.8 76.1,37.8 75.05,36.75
  BOTTOM w0.16: R157.2 73.16,86.65 73.74,87.23 76.08,87.23 76.8,86.51 80.22,86.51 80.96,87.25 81.86,87.25 v1(82.56,86.55)
  BOTTOM w0.2: U21.1 75.66,36.75 76.31,37.4 81.71,37.4 84.71,40.4 88.51,40.4 91.36,43.25 91.36,44.53 C92.1
  BOTTOM w0.3: v2(89.76,47.78) 89.76,47.49 89.34,47.06 C92.1
  BOTTOM w0.4: v2(88.91,57.84) 89.07,58 89.11,58 89.36,58.25 R148.1
USB.OVER_CURRENT: length 110.3
  TOP w0.2: D41.C 95.75,44.92 v1(95.75,44.49) ; v1(96.62,38.16) 94.46,36 76.41,36 76.06,36.35 v2(76.06,38.7)
  POWER PLANE w0.152: v1(75.12,40.94) 79.56,45.39 79.56,62.88 79.81,63.13 79.81,88.4 78.65,89.56 61.97,89.56 61.39,88.97 61.38,88.97 v1(60.86,88.45)
  BOTTOM w0.152: U27.87 60.86,84.02 60.9,84.06 60.9,84.42 60.86,84.46 v1(60.86,88.45) ; U21.3 76.01,38.65 v2(76.06,38.7)
  BOTTOM w0.16: U21.3 74.78,39.66 R146.2 74.97,40.8 v1(75.12,40.94)
  BOTTOM w0.2: v1(96.62,38.16) 96.62,43.61 v1(95.75,44.49)
USB.POWER_SWITCH_ON: length 79.7
  POWER PLANE w0.152: 79.77,88.87 78.84,89.8 78.83,89.8 78.77,89.86 61.52,89.86 v1(61.36,89.7) ; 77.21,40.1 v2(77.21,40.89)
  POWER PLANE w0.16: 79.77,88.87 80.11,88.52 80.11,63.01 80.06,62.95 80.06,43.74 v2(77.21,40.89)
  BOTTOM w0.152: v2(77.21,40.89) 77.21,40.16 R147.2 78.03,40.86 R192.2 ; v1(61.36,89.7) U27.88
  BOTTOM w0.5: U21.4 77.24,40.07 R147.2
VZ1: length 35.2
  TOP w0.3: v1(73.76,19.25) 73.76,19.8 73.56,20 73.56,20.02 72.79,20.8 U8.3 ; v1(72.71,16.4) 72.71,16.15 72.79,16.07 U8.18
  BOTTOM w0.4: v1(72.71,16.4) 72.51,16.2 63.95,16.2 61.22,18.93 D23.C ; v1(73.76,19.25) 69.36,19.25 68.71,18.6 61.04,18.6
  BOTTOM w0.5: J12.2 57.18,18.93 D23.C 61.04,18.6
N15104302: length 2.4
  BOTTOM w0.2: R39.1 79.11,31.55 79.08,31.52 U9.2
N15104306: length 2.4
  BOTTOM w0.2: R42.1 80.34,32.12 U9.3
N15104310: length 2.4
  BOTTOM w0.2: R48.1 81.61,31.03 81.62,31.02 U9.4
N15105235: length 16.1
  TOP w0.25: 68.41,25.1 D19.C 69.66,25.1 70.16,24.6 71.27,24.6 71.51,24.36
  TOP w0.3: v2(79.31,25.67) 78.08,26.91 71.96,26.91 71.5,26.45 71.5,26.24 71.5,26.06 71.5,25.42 71.5,25.42 71.5,25.24 71.5,24.88 71.51,24.87 71.51,24.36
  TOP w0.4: 71.51,24.36 R41.2
  BOTTOM w0.152: U9.7 79.08,24.96 79.31,25.2 v2(79.31,25.67)
N15105303: length 19.4
  TOP w0.2: v2(80.34,25.67) 78.66,27.36 69.07,27.36 66.81,25.1
  TOP w0.25: R43.2 68.84,24.01 68.28,24.57 67.99,24.58 67.68,24.58 67.58,24.68 67.32,24.68 66.9,25.1 66.81,25.1
  TOP w0.3: D20.C 66.81,25.1
  BOTTOM w0.152: U9.6 v2(80.34,25.67)
N15105538: length 1.5
  TOP w0.3: R47.1 69.01,14.64 68.86,14.79 68.86,15.05 68.86,15.79 U8.12
N15105768: length 1.8
  TOP w0.2: R44.1 68.21,14.82 68.23,14.84 U8.11
N15112703: length 19.7
  BOTTOM w0.5: J10.2 54.31,24.54 54.31,21.8 J12.1 54.31,18.6 54.31,16.8 55.71,15.4 56.77,15.4 60.2,11.97 D23.A
N15122676: length 28.4
  TOP w0.2: v3(42.74,52.1) 43.08,52.1 43.39,52.41 U15.1 ; U14.4 30.34,38.07 R86.2
  TOP w0.25: R86.2 29.5,37.23 29.26,37.23 28.76,37.73 28.76,44.65 32.06,47.95 34.43,47.95 37.97,51.49 v3(37.97,52.12)
  POWER PLANE w0.2: v3(37.97,52.12) 38.58,52.12 38.6,52.1 v3(42.74,52.1)
N15122744: length 32.2
  TOP w0.16: v3(34.64,47.1) 34.64,46.39 C128.2 ; U15.2 43.89,51.91 43.62,51.64 v1(43.22,51.64)
  TOP w0.3: TP11.1 35.34,36.03 35.34,36.87 36.61,38.14 D35.C
  TOP w0.35: 37.56,39.23 37.56,42.54 36.84,43.26 C66.2 35.77,44.3
  TOP w0.4: 35.77,44.3 35.77,45.17 34.63,46.31 C128.2 33.58,46.31 C63.1 ; U14.6 34.76,38.72 35.2,38.28 D35.C 37.56,39.23
  POWER PLANE w0.16: v3(34.64,47.1) 34.64,49.29 36.84,51.49 43.07,51.49 v1(43.22,51.64)
N15123033: length 16.7
  TOP w0.2: 38.81,41.1 L1.2
  TOP w0.3: v2(30.51,40.6) 30.51,40.5 U14.1 ; v1(38.11,38.4) 38.11,38 C65.1 38.46,38.43 38.45,38.45 C64.2 C62.2 38.61,40.36 L1.2
  TOP w0.4: L2.1 31,41.09 v2(30.51,40.6)
  BOTTOM w0.3: v1(38.11,38.4) 37.62,38.89 34.22,38.89 32.51,40.6 v2(30.51,40.6)
N15123037: length 5.8
  TOP w0.5: L2.2 33.92,41.24 33.93,41.23 U14.8
  TOP w0.6: D35.A 35.73,40.85 35.36,41.23 33.93,41.23
N15123750: length 1.7
  TOP w0.2: R85.2 30.19,40.01 30.83,39.38 U14.2
N15125008: length 3.8
  TOP w0.3: D9.C 65.24,95.85 64.63,95.24 v2(64.31,95.24)
  BOTTOM w0.3: U3.1 66,94.67 65.75,94.93 65.38,94.93 65.07,95.24 64.92,95.24 v2(64.31,95.24)
N15125401: length 3.9
  TOP w0.3: D12.C 81.4,95.85 81.48,95.77 v2(81.68,95.77)
  BOTTOM w0.3: U6.4 80.22,95.34 80.64,95.77 v2(81.68,95.77)
N15133396: length 29.9
  TOP w0.2: D17.C 75.92,24.7 75.81,24.59 R33.2
  TOP w0.25: v2(75.81,26.2) 75.92,26.09 D17.C
  TOP w0.4: v2(85.31,25.67) 84.81,26.17 82.84,26.17 TP7.1
  BOTTOM w0.3: v2(75.81,26.2) 76.61,27 84.91,27 85.97,25.94 85.97,25.4 85.58,25.02 85.33,25.02 U7.7
  BOTTOM w0.4: v2(85.31,25.67) 85.31,24.23 U7.7
N15133410: length 19.6
  TOP w0.16: 74.82,24.84 74.51,25.15
  TOP w0.25: R35.2 75,23.09 75.16,23.25 75.16,24.47 74.92,24.72 74.92,24.74 74.82,24.84 74.81,24.84 D18.C
  TOP w0.3: v2(74.81,26.3) 74.51,26 74.51,25.15
  BOTTOM w0.3: v2(74.81,26.3) 76.11,27.6 85.51,27.6 86.59,26.52 86.59,24.21
N15220592: length 8.2
  TOP w0.2: U13.32 34.23,30.96 R78.1
  TOP w0.4: R78.1 33.27,31.79 32.79,32.27 32.79,32.36 32.52,32.63 32.52,32.8 31.89,33.43 29.54,33.43 29.14,33.03 R76.2
N15439126: length 1.6
  TOP w0.4: R63.2 55.1,12.26 D24.A
N15439189: length 1.6
  TOP w0.4: D25.A 50.05,12.26 R66.2
N15439310: length 1.7
  TOP w0.4: D26.A 44.3,12.2 44.28,12.21 43.56,12.21 R67.2
N15439443: length 1.7
  TOP w0.4: R70.2 39.13,12.26 39.2,12.2 D28.A
N15439617: length 1.6
  TOP w0.4: D30.A 35.1,12.26 R73.2
N15439707: length 1.5
  TOP w0.4: R77.2 30.42,12.26 D31.A
N15439797: length 1.5
  TOP w0.4: D32.A 25.22,12.26 R79.2
N15439887: length 1.5
  TOP w0.4: D33.A 20.17,12.26 R80.2
N15474250: length 1.6
  TOP w0.2: R25.2 91.11,102.25 91.31,102.05 U5.9
N15474355: length 1.6
  TOP w0.2: C25.1 91.11,101.4 91.26,101.55 U5.10
N15474517: length 1.5
  TOP w0.2: C27.1 91.11,99.05 U5.15
N15476731: length 1.6
  TOP w0.25: U4.9 51.75,102.02 R23.2
N15476759: length 1.6
  TOP w0.3: U4.10 52.33,101.52 52.11,101.3 C19.1
N15476871: length 1.7
  TOP w0.25: R24.2 51.75,99.52 U4.14
N15476899: length 1.6
  TOP w0.25: C21.1 52.06,98.95 52.13,99.02 U4.15
N15484919: length 7.2
  BOTTOM w0.2: R156.1 R154.1 R155.1 57.67,57.36 58.36,58.05 58.36,58.44 58.35,58.45 58.35,58.83 58.36,58.84 U27.27
N15485310: length 8.7
  LOGIC_PLANE w0.2: 55.71,59.43 v1(55.71,59.4) v1(55.71,55.2)
  BOTTOM w0.2: R168.1 56.12,55.2 v1(55.71,55.2) ; C112.2 C111.1 ; 55.71,59.11 v1(55.71,59.4) 55.71,59.85 55.86,60
  BOTTOM w0.25: 55.71,59.11 C112.2 ; 55.86,60 U27.32
N15486514: length 2.9
  BOTTOM w0.3: C102.1 49.86,80.1 50.26,80.5 U27.71
N15487467: length 12.1
  TOP w0.2: v2(72.51,82.8) 70.91,81.2 68.51,81.2 v1(67.91,81.8)
  BOTTOM w0.2: U27.101 67.86,81.85 v1(67.91,81.8) ; R157.1 73.16,83.45 v2(72.51,82.8)
  BOTTOM w0.25: R158.1 67.81,84.85 67.86,84.8 U27.101
N15487548: length 5.7
  BOTTOM w0.2: C101.2 71.92,85 71.92,84.42 71.91,84.41 71.91,82.34 71.57,82 70.79,82 70.65,82 70.36,82.29 U27.106
N15498231: length 25.6
  TOP w0.3: C103.1 55.78,64.36 v1(55.35,63.93)
  LOGIC_PLANE w0.22: 55.21,59.4 55.21,57.68 55.21,57.67 55.21,57.42
  LOGIC_PLANE w0.25: v1(55.35,63.93) 55.35,59.84 55.21,59.7 55.21,59.4 ; 55.21,57.42 55.04,57.26 55.04,55.99 55.11,55.92 v1(55.11,55.4)
  LOGIC_PLANE w0.4: v1(51.14,50.58) 51.16,50.61 51.24,50.61 51.63,51 v1(52.71,51)
  BOTTOM w0.2: C105.1 58.77,53.41 57.82,54.81 C104.1 56.64,53.84 R168.2
  BOTTOM w0.25: v1(55.11,55.4) 55.11,55.13 55.51,54.72 55.59,54.72 56.47,53.84 56.55,53.84 ; v1(55.35,63.93) 55.35,63.4 55.36,63.4 U27.33
  BOTTOM w0.3: 56.55,53.84 R168.2
  BOTTOM w0.4: v1(52.71,51) 53.31,51.6 53.91,51.6 55.91,53.6 56.31,53.6 56.55,53.84
  BOTTOM w0.5: L6.2 50.91,50.36 v1(51.14,50.58)
N15498429: length 2.3
  BOTTOM w0.35: 88.53,93.98 88.53,95.58 R172.2
N15498461: length 3.2
  BOTTOM w0.3: R174.2 R175.2
  BOTTOM w0.5: U28.3 89.8,95.13 90.11,95.45 R175.2
N15499136: length 2.5
  BOTTOM w0.2: 68.96,57.79 C124.1 R173.1 68.16,56.3 Y1.2
N15499220: length 1.4
  BOTTOM w0.2: R178.1 59.85,57.97 60.64,57.18 Y2.3
N15499244: length 2.8
  BOTTOM w0.2: R180.1 C125.1 66.46,57 Y1.1
N15499420: length 1.1
  BOTTOM w0.2: R183.2 59.05,55.14 Y2.1
N15511092: length 11.8
  TOP w0.3: v2(39.16,43.51) 39.17,43.51 39.36,43.7 Q1.3 ; U14.7 34.59,39.38 v2(34.71,39.5)
  TOP w0.4: v1(42.13,43.55) 41.98,43.7 Q1.3
  BOTTOM w0.3: v2(39.16,43.51) 35.62,39.96 35.17,39.96 v2(34.71,39.5) ; R83.2 43.25,43.59 43.21,43.55 v1(42.13,43.55)
